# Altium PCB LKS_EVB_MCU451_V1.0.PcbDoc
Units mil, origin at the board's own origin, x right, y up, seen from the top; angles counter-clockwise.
Board outline 8180 x 3528.01 mil, 2 copper layers (Top Layer, Bottom Layer); 102 components, 121 nets, 428 pads, 143 vias.
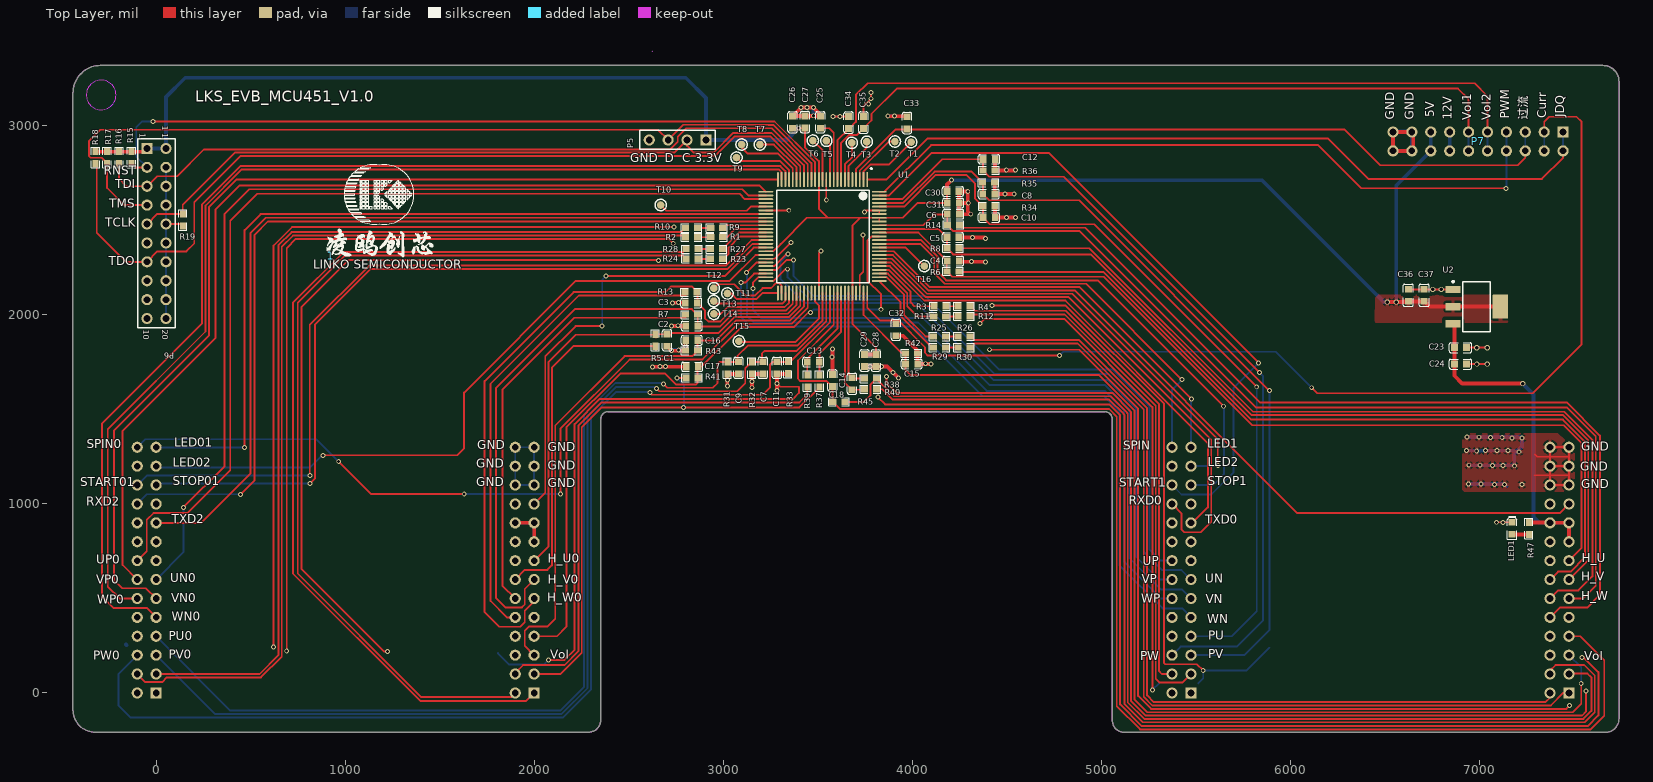
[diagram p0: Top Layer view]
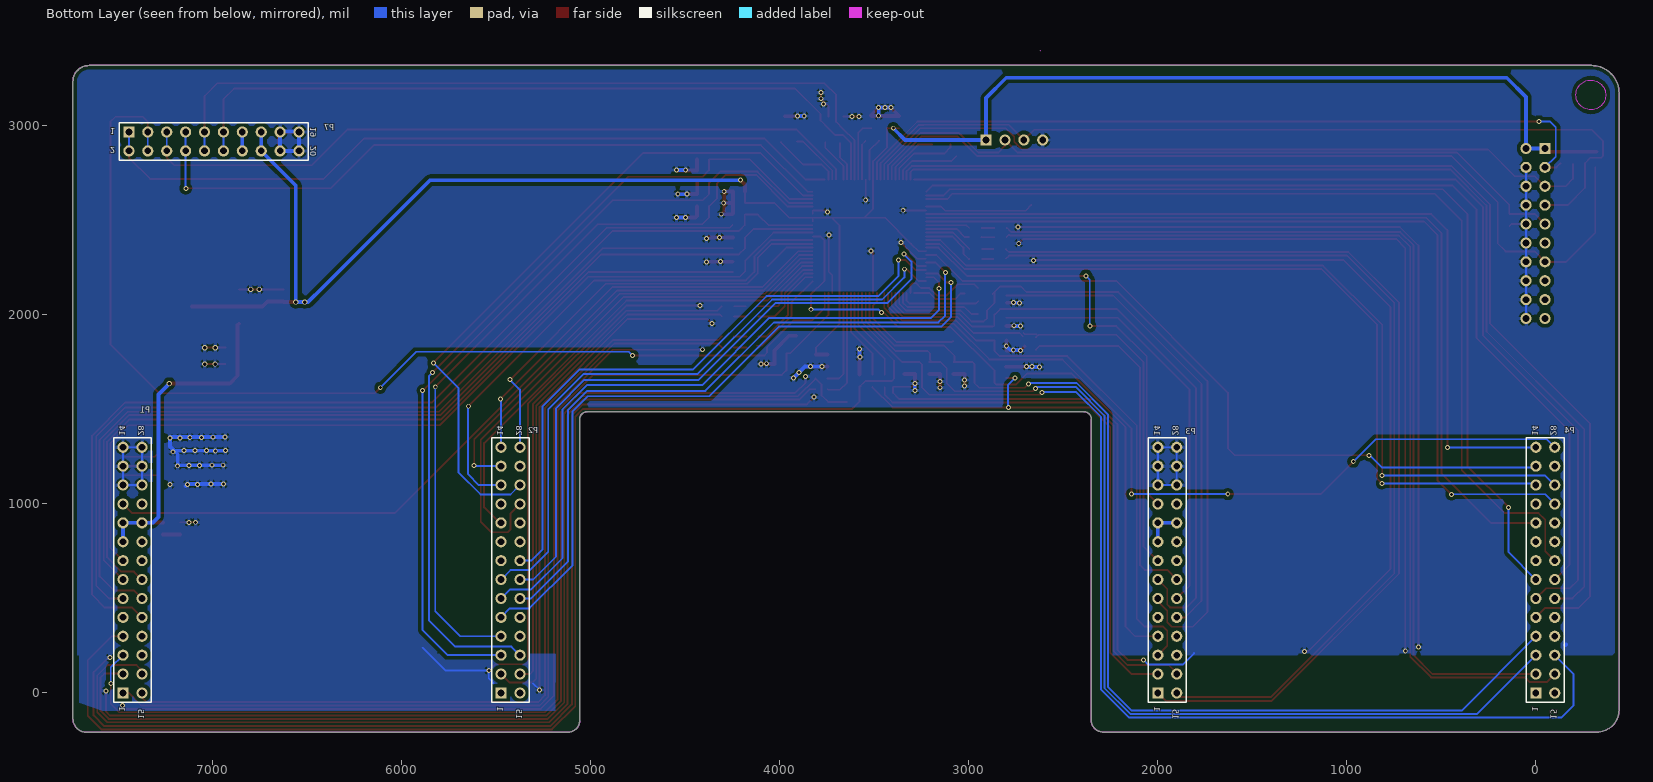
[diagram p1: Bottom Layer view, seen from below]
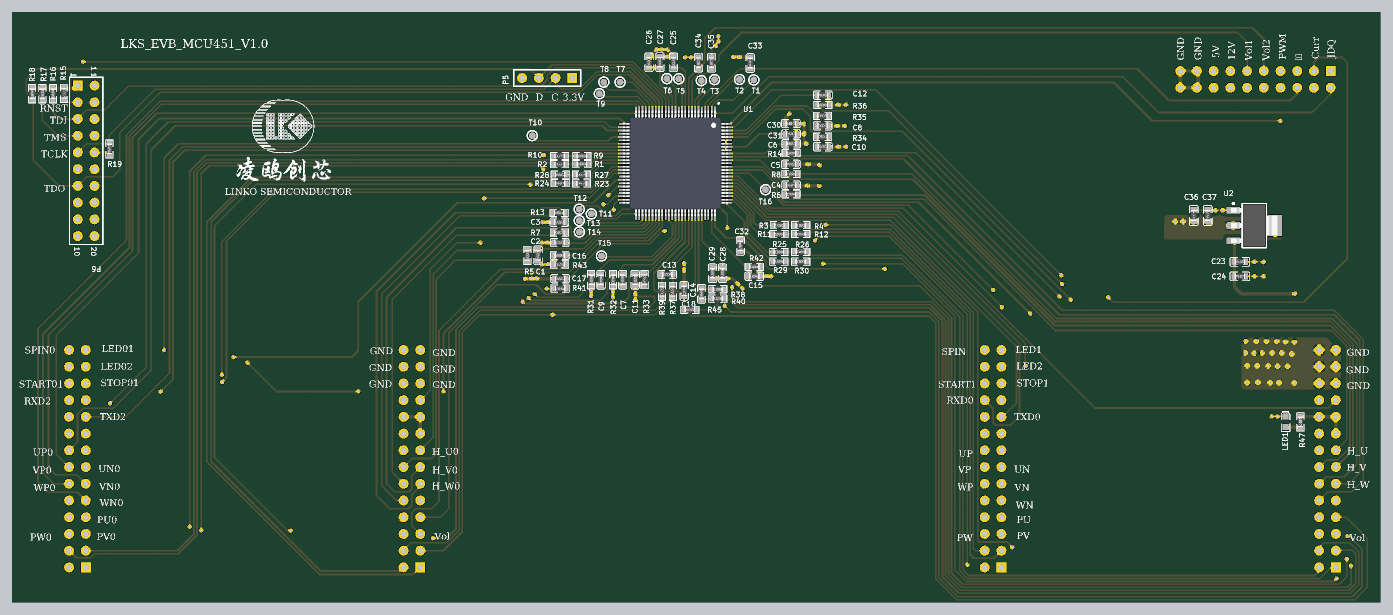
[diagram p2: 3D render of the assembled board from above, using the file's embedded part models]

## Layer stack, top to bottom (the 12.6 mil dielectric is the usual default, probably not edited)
Top Solder: solder mask 0.4, Solder Resist, Dk 3.5
Top Layer: signal copper 1.4
Dielectric1: dielectric 12.6, FR-4, Dk 4.8
Bottom Layer: signal copper 1.4
Bottom Solder: solder mask 0.4, Solder Resist, Dk 3.5

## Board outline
-440,-91 ccw(c-324,-91) -324,-207 2288.99,-207 ccw(c2288.99,-143.67) 2352.32,-143.67 2352.32,1448.33 cw(c2392,1448.33) 2392,1488.01 5018,1488.01 cw(c5018,1446.67) 5059.33,1446.67 5059.33,-146.33 ccw(c5121,-146.33) 5121,-208 7669,-208 ccw(c7669,-137) 7740,-137 7740,3235 ccw(c7654.99,3235) 7654.99,3320.01 -294.32,3320.01 ccw(c-294.32,3174.33) -440,3174.33

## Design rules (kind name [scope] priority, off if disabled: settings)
Clearance Clearance_1 [INPolygon] p1: gap=20 ignorepadtopadclearanceinfootprint=FALSE except(0: Arc-Hole Track-Hole SMDPad-Hole THPad-Hole Via-Hole Fill-Hole Poly-Hole Region-Hole Text-Hole)
Clearance [All] p2: gap=7.87 ignorepadtopadclearanceinfootprint=FALSE except(0: Arc-Hole Track-Hole SMDPad-Hole THPad-Hole Via-Hole Fill-Hole Poly-Hole Region-Hole Text-Hole)
ComponentClearance [All] p1: gap=0 collisioncheckmode=3 verticalgap=0 showdistances=FALSE
MinimumSolderMaskSliver [All] p1 off: minsoldermaskwidth=10
PolygonConnect [All] p1: connectstyle=Relief reliefconductorwidth=20 reliefentries=4 polygonreliefangle="90 Angle" airgapwidth=10
RoutingVias [All] p1: holewidth=28 width=50 viastyle="Through Hole" minholewidth=28 minwidth=50 maxholewidth=28 maxwidth=50
SilkToSilkClearance [All] p1 off: silktosilkclearance=10
SilkToSolderMaskClearance SilkscreenOverComponentPads [IsPad] p1 off: minsilkscreentomaskgap=10 clearancetoexposedcopper=TRUE
SolderMaskExpansion [All] p1: expansion=4 istentingtop=FALSE
Width [All] p1: maxlimit=100 minlimit=1 preferedwidth=10
26 further rules are at their usual default settings.

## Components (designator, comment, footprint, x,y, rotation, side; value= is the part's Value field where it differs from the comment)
1 "LKS_sign" LKS_LOGO2 924,2313 r0 top
C1 "10nF/16V" 0603C 2704,1866 r270 top
C2 "10nF/16V" 0603C 2833.5,1941.99 r180 top
C3 "10nF/16V" 0603C 2831.67,2063.99 r180 top
C4 "10nF/16V" 0603C 4217,2285 r0 top
C5 "10nF/16V" 0603C 4216,2410 r0 top
C6 "10nF/16V" 0603C 4218,2533 r0 top
C7 "1nF/16V" 0603C 3210,1720 r270 top
C8 "1nF/16V" 0603C 4406,2640 r0 top
C9 "1nF/16V" 0603C 3081,1720 r270 top
C10 "1nF/16V" 0603C 4407,2515 r0 top
C11 "1nF/16V" 0603C 3285,1720 r270 top
C12 "1nF/16V" 0603C 4407.01,2823.67 r0 top
C13 "1nF/10V" 0603C 3477,1751 r180 top
C14 "1nF/10V" 0603C 3682,1636 r270 top
C15 "100nF/50V" 0603C 3997,1741 r180 top
C16 "100nF/50V" 0603C 2834.01,1865.67 r0 top
C17 "1nF/50V" 0603C 2836,1726 r0 top
C18 "1nF/50V" 0603C 3578,1653 r270 top
C23 "10uF/10V" 0603C 6901,1827 r0 top
C24 "100nF/10V" 0603C 6901,1740 r0 top
C25 "100nF/50V" 0603C 3514,3020 r90 top
C26 "10uF/10V" 0603C 3368,3020 r90 top
C27 "100nF/10V" 0603C 3432.67,3020.99 r90 top
C28 "10uF/10V" 0603C 3808,1759 r270 top
C29 "100nF/10V" 0603C 3748,1759 r270 top
C30 "10uF/10V" 0603C 4216.01,2653.67 r0 top
C31 "100nF/10V" 0603C 4217,2592 r0 top
C32 "100pF/10V" 0603C 3914,1922 r270 top
C33 "100pF/10V" 0603C 3973,3016 r90 top
C34 "100pF/10V" 0603C 3664,3018 r90 top
C35 "100pF/10V" 0603C 3742,3018 r90 top
C36 "10uF/10V" 0603C 6625,2104 r90 top
C37 "100nF/10V" 0603C 6709,2104 r90 top
LED1 "LED" 0603D 7174,871 r90 top
P1 "Header 14X2A" HDR2X14_CEN 7475,0 r90 bottom
P2 "Header 14X2A" HDR2X14_CEN 5475,0 r90 bottom locked
P3 "Header 14X2A" HDR2X14_CEN 2000,0 r90 bottom locked
P4 "Header 14X2A" HDR2X14_CEN 0,0 r90 bottom locked
P5 "Header 4" HDR1X4 2909,2926 r180 top
P6 "Header 10X2A" HDR2X10_CEN -48,2881 r270 top
P7 "Header 10X2" HDR2X10 7444,2968 r180 top locked
R1 "20K1%" 0603R 2966,2411.5 r0 top value=K
R2 "20K1%" 0603R 2833,2411 r0 top value=K
R3 "20K1%" 0603R 4147,2046 r180 top value=K
R4 "20K1%" 0603R 4275,2046 r180 top value=K
R5 "2K" 0603R 2641,1866 r90 top value=K
R6 "2K" 0603R 4217,2231 r180 top value=K
R7 "2K" 0603R 2832,2002 r0 top value=K
R8 "2K" 0603R 4216,2353 r180 top value=K
R9 "20K1%" 0603R 2966,2460 r0 top value=K
R10 "20K1%" 0603R 2833,2460 r0 top value=K
R11 "20K1%" 0603R 4146,1992.5 r180 top value=K
R12 "20K1%" 0603R 4275,1993 r180 top value=K
R13 "2K" 0603R 2830,2120 r0 top value=K
R14 "2K" 0603R 4218,2477 r180 top value=K
R15 "10K" 0603R -130,2834 r270 top value=330
R16 "10K" 0603R -196,2832 r270 top value=330
R17 "10K" 0603R -260,2832 r270 top value=330
R18 "10K" 0603R -321,2832 r270 top value=330
R19 "10K" 0603R 141,2502 r90 top value=330
R23 "20K1%" 0603R 2964,2296 r0 top value=K
R24 "20K1%" 0603R 2836,2297 r0 top value=K
R25 "20K1%" 0603R 4144,1886 r180 top value=K
R26 "20K1%" 0603R 4275,1887 r180 top value=K
R27 "20K1%" 0603R 2964,2348 r0 top value=K
R28 "20K1%" 0603R 2836,2348 r0 top value=K
R29 "20K1%" 0603R 4144,1828 r180 top value=K
R30 "20K1%" 0603R 4275,1828 r180 top value=K
R31 "1K" 0603R 3022,1720 r270 top value=K
R32 "1K" 0603R 3152,1720 r270 top value=K
R33 "1K" 0603R 3342,1721 r270 top value=K
R34 "1K" 0603R 4406,2575 r0 top value=K
R35 "1K" 0603R 4405,2700 r0 top value=K
R36 "1K" 0603R 4407,2765 r0 top value=K
R37 "1K1%" 0603R 3510,1650 r90 top value=K
R38 "1K1%" 0603R 3779,1663 r180 top value=K
R39 "1K1%" 0603R 3445.33,1650.01 r90 top value=K
R40 "1K1%" 0603R 3779,1607 r180 top value=K
R41 "1K1%" 0603R 2836,1667 r180 top value=K
R42 "1K1%" 0603R 3997,1797 r180 top value=K
R43 "1K1%" 0603R 2833,1811 r0 top value=K
R45 "1K1%" 0603R 3612,1540 r0 top value=K
R47 "330R" 0603R 7263,870 r270 top value=330
T1 "TestP" TP-40 3995,2915 r0 top
T2 "TestP" TP-40 3909,2918 r0 top
T3 "TestP" TP-40 3760,2917 r0 top
T4 "TestP" TP-40 3681,2911 r0 top
T5 "TestP" TP-40 3546,2922 r0 top
T6 "TestP" TP-40 3475,2923 r0 top
T7 "TestP" TP-40 3195,2902 r0 top
T8 "TestP" TP-40 3098,2902 r0 top
T9 "TestP" TP-40 3071,2833 r0 top
T10 "TestP" TP-40 2669,2582 r90 top
T11 "TestP" TP-40 3023,2114 r0 top
T12 "TestP" TP-40 2950,2142 r90 top
T13 "TestP" TP-40 2950,2074 r90 top
T14 "TestP" TP-40 2951,2006 r90 top
T15 "TestP" TP-40 3083,1862 r90 top
T16 "TestP" TP-40 4064,2259 r90 top
U1 "LKS451" LQFP_100N 3526.01,2415.67 r270 top locked
U2 "AMS1117-3.3V" DCY0004A_M 6987,2044 r0 top

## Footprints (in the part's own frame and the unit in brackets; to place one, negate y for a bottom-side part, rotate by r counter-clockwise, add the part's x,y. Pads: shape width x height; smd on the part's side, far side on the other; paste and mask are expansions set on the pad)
0603C [mm]
  rect 0.9x0.95 smd: 1(-0.813,0) 2(0.813,0)
  silkscreen extent -1.42,-0.64 1.42,0.64, body extent -0.8,-0.4 0.8,0.4, height 0.45
0603D [mm]
  rect 0.9x0.9 smd: 1(-0.813,0) 2(0.813,0)
  silkscreen extent -1.47,-0.66 1.65,0.66
0603R [mil]
  rect 38x32 smd: 1(-32,0) 2(32,0)
  silkscreen extent -54,-22 54,22, body extent -31,-16 32,16, height 18
DCY0004A_M [mm] "SOT223, 4-Leads, Body 6.7x3.7mm, Pitch 2.3mm, IPC Low Density"
  rrect10% 2.05x1 smd: 1(-3.175,2.3) 2(-3.175,0) 3(-3.175,-2.3)
  rrect5% 2.05x3.25 smd: 4(3.175,0)
  silkscreen extent -3.3,-3.35 1.85,3.47, body extent -3.5,-3.25 3.5,3.25, height 1.62
HDR1X4 [mm] "Connector; Header; 4 Position"
  rect 1.5x1.5 hole 0.9: 1(0,0)
  round 1.5 hole 0.9: 2(2.54,0) 3(5.08,0) 4(7.62,0)
  silkscreen extent -1.27,-1.27 8.89,1.27
HDR2X10 [mm] "Connector; Header; 10x2 Position"
  rect 1.5x1.5 hole 0.9: 1(0,0)
  round 1.5 hole 0.9: 2(0,2.54) 3(2.54,0) 4(2.54,2.54) 5(5.08,0) 6(5.08,2.54) 7(7.62,0) 8(7.62,2.54) 9(10.16,0) 10(10.16,2.54) 11(12.7,0) 12(12.7,2.54) 13(15.24,0) 14(15.24,2.54) 15(17.78,0) 16(17.78,2.54) 17(20.32,0) 18(20.32,2.54) 19(22.86,0) 20(22.86,2.54)
HDR2X10_CEN [mm] "Connector; Header; 10x2 Position"
  rect 1.5x1.5 hole 0.9: 1(0,0)
  round 1.5 hole 0.9: 2(2.54,0) 3(5.08,0) 4(7.62,0) 5(10.16,0) 6(12.7,0) 7(15.24,0) 8(17.78,0) 9(20.32,0) 10(22.86,0) 11(0,2.54) 12(2.54,2.54) 13(5.08,2.54) 14(7.62,2.54) 15(10.16,2.54) 16(12.7,2.54) 17(15.24,2.54) 18(17.78,2.54) 19(20.32,2.54) 20(22.86,2.54)
  silkscreen extent -1.27,-1.27 24.13,3.81
HDR2X14_CEN [mm] "Connector; Header; 14x2 Position"
  rect 1.5x1.5 hole 0.9: 1(0,0)
  round 1.5 hole 0.9: 2(2.54,0) 3(5.08,0) 4(7.62,0) 5(10.16,0) 6(12.7,0) 7(15.24,0) 8(17.78,0) 9(20.32,0) 10(22.86,0) 11(25.4,0) 12(27.94,0) 13(30.48,0) 14(33.02,0) 15(0,-2.54) 16(2.54,-2.54) 17(5.08,-2.54) 18(7.62,-2.54) 19(10.16,-2.54) 20(12.7,-2.54) 21(15.24,-2.54) 22(17.78,-2.54) 23(20.32,-2.54) 24(22.86,-2.54) 25(25.4,-2.54) 26(27.94,-2.54) 27(30.48,-2.54) 28(33.02,-2.54)
  silkscreen extent -1.27,-3.81 34.29,1.27
LKS_LOGO2 [mil] "标?"
  silkscreen extent 70,167 440,482
LQFP_100N [mm] "TSQFP, 100-Leads, Body 16,0x16,0mm (max), Pitch 0,50mm, IPC Medium Density"
  rect 2x0.25 smd: 1(-7.625,6)
  oval 2x0.25 smd: 2(-7.625,5.5) 3(-7.625,5) 4(-7.625,4.5) 5(-7.625,4) 6(-7.625,3.5) 7(-7.625,3) 8(-7.625,2.5) 9(-7.625,2) 10(-7.625,1.5) 11(-7.625,1) 12(-7.625,0.5) 13(-7.625,0) 14(-7.625,-0.5) 15(-7.625,-1) 16(-7.625,-1.5) 17(-7.625,-2) 18(-7.625,-2.5) 19(-7.625,-3) 20(-7.625,-3.5) 21(-7.625,-4) 22(-7.625,-4.5) 23(-7.625,-5) 24(-7.625,-5.5) 25(-7.625,-6) 51(7.625,-6) 52(7.625,-5.5) 53(7.625,-5) 54(7.625,-4.5) 55(7.625,-4) 56(7.625,-3.5) 57(7.625,-3) 58(7.625,-2.5) 59(7.625,-2) 60(7.625,-1.5) 61(7.625,-1) 62(7.625,-0.5) 63(7.625,0) 64(7.625,0.5) 65(7.625,1) 66(7.625,1.5) 67(7.625,2) 68(7.625,2.5) 69(7.625,3) 70(7.625,3.5) 71(7.625,4) 72(7.625,4.5) 73(7.625,5) 74(7.625,5.5) 75(7.625,6)
  oval 0.25x2 smd: 26(-6,-7.625) 27(-5.5,-7.625) 28(-5,-7.625) 29(-4.5,-7.625) 30(-4,-7.625) 31(-3.5,-7.625) 32(-3,-7.625) 33(-2.5,-7.625) 34(-2,-7.625) 35(-1.5,-7.625) 36(-1,-7.625) 37(-0.5,-7.625) 38(0,-7.625) 39(0.5,-7.625) 40(1,-7.625) 41(1.5,-7.625) 42(2,-7.625) 43(2.5,-7.625) 44(3,-7.625) 45(3.5,-7.625) 46(4,-7.625) 47(4.5,-7.625) 48(5,-7.625) 49(5.5,-7.625) 50(6,-7.625) 76(6,7.625) 77(5.5,7.625) 78(5,7.625) 79(4.5,7.625) 80(4,7.625) 81(3.5,7.625) 82(3,7.625) 83(2.5,7.625) 84(2,7.625) 85(1.5,7.625) 86(1,7.625) 87(0.5,7.625) 88(0,7.625) 89(-0.5,7.625) 90(-1,7.625) 91(-1.5,7.625) 92(-2,7.625) 93(-2.5,7.625) 94(-3,7.625) 95(-3.5,7.625) 96(-4,7.625) 97(-4.5,7.625) 98(-5,7.625) 99(-5.5,7.625) 100(-6,7.625)
  silkscreen extent -9.22,-6.12 6.22,6.66, body extent -8,-8 8,8, height 1.61
TP-40 [mil] "测试"
  round 40 smd: 1(-0.39,-0.39)
  silkscreen extent -30,-30 30,30

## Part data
C1 C2 C3 C4 C5 C6 C7 C8 C9 C10 C11 C12: library part CAP, "Capacitor"
C13 C14 C15 C16 C17 C18 C23 C24 C25 C26 C27 C28 C29 C30 C31 C32 C33 C34 C35 C36 C37: library part C, "Capacitor"
LED1: "LED_Light"
P1 P2 P3 P4: "Header, 14-Pin, Dual row"
P5: "Header, 4-Pin"
P6 P7: "Header, 10-Pin, Dual row"
R1 R2 R3 R4 R5 R6 R7 R8 R9 R10 R11 R12 R13 R14 R15 R16 R17 R18 R19 R23 R24 R25 R26 R27 R28 R29 R30 R31 R32 R33 R34 R35 R36 R37 R38 R39 R40 R41 R42 R43 R45 R47: library part Res, "Resistor"
U1: library part LKS32MC451VCT8, "LKS32MC451VCT8--chip"
U2: library part CMP-019-00008-2, "Low-Dropout Linear Regulator, 1 A, 3.3 V, 0 to 125 degC, 4-Pin SOT223 (DCY), RoHS, Tape and Reel", Case/Package=SOT-223, Dropout Voltage=1.2V, Manufacturer="Texas Instruments", Max Input Voltage=15V, Max Operating Temperature=125°C, Max Ouput Current=1A, Min Input Voltage=2.5V, Min Operating Temperature=0°C, Min Supply Voltage=3.2V, Nominal Supply Current=5mA, Output Voltage=3.3V, Package Description="4-Pin Small Outline Transistor, Body 6.5 x 3.5 mm, Pitch 2.3 mm", Package Quantity=1000, Package Reference=DCY0004A

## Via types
v1: diameter 26, hole 16, Top Layer to Bottom Layer, 133 vias
v2: diameter 28, hole 18, Top Layer to Bottom Layer, 9 vias
v3: diameter 23.62, hole 15.75, Top Layer to Bottom Layer, 1 vias

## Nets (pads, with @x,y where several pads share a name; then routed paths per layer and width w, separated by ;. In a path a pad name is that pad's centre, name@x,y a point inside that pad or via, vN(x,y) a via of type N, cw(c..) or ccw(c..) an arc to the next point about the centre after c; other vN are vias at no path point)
5V: P3.9 P3.10 P3.24 | length 400
  Top Layer w20: P3.24 P3.10 P3.9
  Bottom Layer w20: P3.24 P3.10 P3.9
12V: P7.13 P7.14 | length 100
  Bottom Layer w20: P7.14 P7.13
+3.3V: C26.1 C27.1 C28.1 C29.1 C30.1 C31.1 C36.1 C37.1 P5.1 P6.1 P6.11 P7.15 P7.16 R15.1 R16.1 R17.1 R18.1 U1.14 U1.42 U1.71 U1.92 U1.93 U2.2 U2.4 | length 11199
  Top Layer w9.84: C26.1 v1(3399.84,2988) 3431.68,2988 C27.1 3432.67,2887.6 3506.32,2813.95 U1.14 3506.32,2560.68 3552.9,2514.1 3725,2514.1 ; C28.1 3808,1829 3683.49,1953.51 U1.71 3683.49,2472.59 3725,2514.1 ; U1.92 U1.93 ; C30.1 4185,2652.68 C31.1 4027,2592 3949.1,2514.1 U1.93 ; 3725,2514.1 U1.93
  Top Layer w10: U1.42 3225.89,2337.01 3265.82,2337.01 3304,2375.19 3442.91,2514.1 3552.9,2514.1
  Top Layer w20: R18.1 R17.1 R16.1 -130,2864 -65,2864 P6.1 ; C29.1 C28.1 ; C30.1@4185,2652.68 4185,2690 v1(4208,2713) ; v2(6514,2068) v2(6561,2068) ; v2@6561,2069 6623,2069 6625,2071 6625.5,2071.5 6708.5,2071.5 C37.1 6709.98,2072 6737.98,2044 U2.2 U2.4
  Bottom Layer w20: P6.1 P6.11 52,3153 154,3255 2802,3255 2909,3148 P5.1 3337.84,2926 v1(3399.84,2988) ; v1(4208,2713) 5851,2713 6417.5,2146.5 6496,2068 v2(6514,2068) v2(6561,2068) 6561,2685 P7.16 P7.15
+5V: C23.1 C24.1 P1.9 P1.10 P1.24 R47.1 U2.3 | length 1999
  Top Layer w20: U2.3 6869,1946.45 C23.1 C24.1 6869,1678 6910,1637 v2(7230,1637) ; R47.1 7373,902 P1.24 P1.10 P1.9
  Bottom Layer w20: v2(7230,1637) 7288,1579 7288,1521 7288,931 7319,900 P1.24 P1.10 P1.9
GND: C1.2 C2.2 C3.2 C4.2 C5.2 C6.2 C7.2 C8.2 C9.2 C10.2 C11.2 C12.2 C15.1 C16.1 C17.1 C18.1 C23.2 C24.2 C25.2 C26.2 C27.2 C28.2 C29.2 C30.2 C31.2 C32.2 C33.2 C34.2 C35.2 C36.2 C37.2 LED1.2 P1.12 P1.13 P1.14 P1.26 P1.27 P1.28 P3.12 P3.13 P3.14 P3.26 P3.27 P3.28 P5.4 P6.12 P6.13 P6.14 P6.15 P6.16 P6.17 P6.18 P6.19 P6.20 P7.17 P7.18 P7.19 P7.20 R19.1 R31.2 R32.2 R33.2 R34.2 R35.2 R36.2 R42.1 R43.1 U1.12 U1.31 U1.44 U1.62 U1.73 U1.94 U1.95 U2.1 | length 48278.9
  Top Layer w9.84: P6.15 130,2481 R19.1 ; U1.44 3273.56,2297.56 v1(3360,2384) ; U1.31 v3(3348,2553.47) ; U1.62 3506.32,2326.32 v1(3518,2338) ; v1(3545.69,2607.31) U1.12 ; U1.73 3722.86,2210.86 3741,2229 v1(3741,2422) ; v1(3748,2545) 3756.47,2553.47 U1.95 U1.94 ; v1(7091,903) LED1.2 ; 7292,1152 7375,1152 ; 7294,1263 7307.12,1249.88 7375,1249.88 ; P1.28 7375,1249.88 ; P1.28@7395,1302 7473,1302 P1.14 P1.13 ; 7474.11,1149.16 7471.27,1152 7375,1152 ; 7474.27,1249.88 7375,1249.88 ; 7375,1152 P1.26 P1.12 P1.13 ; 7375,1152 P1.27 ; P1.27 P1.13 ; P1.27 7375,1249.88
  Top Layer w10: v1(621,243) 621,2367.17 718.83,2465 v1(2739.18,2465) ; v1(691,221) 691,2354 739.49,2402.49 2712.51,2402.49 v1(2736,2379) ; v1(1225,220) 1205,220 770,655 770,2043 1018,2291 v1@2659,2291 ; v1(2076,175) 2160,175 2214,229 2214,1422.83 2347.17,1556 3370,1556 3401,1587 3401,1620 3302,1620 v1@3285,1637 ; v1(3582,3050) v1(3618,3050) C34.2 ; C35.2 3742,3103 v1(3783,3144) v1(3783,3176) ; v1(3819,1565) 3857,1527 5043,1527 5100.59,1469.41 5100.59,-60.59 5215,-175 7574.53,-175 7631,-118.53 7631,110 7554,187 v1(7544,187) ; v1(3864,1675) 3864,1642 3918.49,1587.51 5057.88,1587.51 5153.9,1491.49 5153.9,1489.32 5158.51,1484.71 5158.51,-43.12 5235.16,-119.77 7544.06,-119.77 7566,-97.83 v1(7566,10) ; v1(4360,1955) 4384,1979 4804.83,1979 5271.2,1512.63 v1(5271.2,15.8) ; v1(4409,1816) 4883.83,1816 5195,1504.83 5195,-15.22 5263.96,-84.18 7461.82,-84.18 v1(7479,-67) ; v1(4423,2049) 4812.83,2049 5332.6,1529.24 5332.6,1282.44 5333,1282.04 5333,1217.96 5332.6,1217.56 5332.6,158.4 5339,152 5507,152 v1(5540,119) ; C36.2@6625,2135 6625.45,2134.55 6755,2134.55 U2.1 ; C24.2 v2(6988,1740) v2(7043,1740) ; C23.2 v2(6987.5,1827) 7042,1827 v2(7043,1826)
  Top Layer w20: v1(2626,1725) 2627,1726 C17.1 ; C1.2 v1(2727,1811) R43.1 2801,1864.67 C16.1 ; v1(2727.01,1941.99) C2.2 ; v1(2731,2064) C3.2 ; v1(3022,1623) v1(3022,1655.5) R31.2 C9.2 ; v1(3152,1615) v1(3152,1648) R32.2 C7.2 ; v1(3285,1600) 3285,1637 C11.2 3341,1688 R33.2 ; C25.2 3477,3052 C26.2 v1(3413,3097) v1(3444,3097) v1(3477,3097) C25.2@3519,3055 ; C18.1 v1(3578,1819) ; C29.2 v1(3778,1727) C28.2 v1(3838,1727) 3868,1727 v1(3899,1696) v1@3927.5,1667.5 ; v1@3871,3051 C33.2@3973,3051 ; C32.2 3951,1890 4029,1812 R42.1 C15.1 v1(4099,1741) ; C5.2 v1(4319,2410) 4383,2410 v1(4389,2404) ; C4.2@4249,2282 v1(4315,2282) 4387,2282 v1(4388,2281) ; C31.2 v1@4294.33,2592 ; v1@4295,2653 v1(4294.33,2653.67) ; v1@4298,2593 v1(4297,2592) v1@4294.33,2592 ; R35.2 4437,2641 C8.2 v1(4540,2640) ; R34.2 4438,2523 4446,2515 v1@4486,2515 ; R36.2 4545,2765 v1(4547,2767) ; R36.2 C12.2 ; v1(4499,2515) v1(4547,2515) ; P7.17 P7.19 P7.20 P7.18 6651,2875 P7.17@6651,2972 ; v1@4294.33,2592 v1(4294.33,2653.67) ; v1@4294.33,2592 4294.33,2548.67 v1(4310,2533) C6.2 4248.01,2534.99 C30.2 v1(4294.33,2653.67)
  Bottom Layer w9.84: P6.20 P6.19 P6.18 P6.17 P6.16 P6.15 P6.14 P6.13 P6.12 ; P3.28 P3.27 P3.26 P3.12 P3.13 P3.14 1928,1300 P3.28@1920,1292 ; P1.28@7374,1303 7377,1300 P1.14 P1.13 P1.12 P1.26 P1.27 P1.28
  Bottom Layer w10: 1808,211 1869,150 2051,150 v1(2076,175) ; v1(5271.2,15.8) 5306.41,51 ; 5514,51 5540,77 v1(5540,119) 5770,119 5890,239
  Bottom Layer w20: -160,256 -156.6,252.6 ; v1(2626,1725) 2692,1725 v1(2695,1728) ; v1(2727,1811) 2730,1814 v1(2765,1814) 2781,1814 v1(2802,1835) ; v1(2727.01,1941.99) 2759.99,1941.99 v1(2761,1943) ; v1(2731,2064) 2762,2064 v1(2763,2065) ; v1(3285,1600) 3286,1601 v1(3286,1637) ; v1(3413,3097) v1(3444,3097) v1(3477,3097) v1(3477,3054) ; v1(3577,1778) 3578,1779 v1(3578,1819) ; v1(3778,1727) v1(3838,1727) 3867,1727 v1(3927,1667) ; v1(3871,3053) v1(3907,3053) ; v1(4492,2639) 4539,2639 v1(4540,2640) ; v1(4498,2767) v1(4547,2767) ; v1(4499,2515) v1(4547,2515) ; P7.19 P7.20 P7.18 P7.17 6640,2972 P7.19@6545,2972 ; v1(6934,1282) v1(7033,1282) v1(7094,1282) v1(7152,1282) v1@7205,1282 ; v1(6935,1354) 7122,1354 7221,1354 v1(7227,1348) 7227,1304 v1@7205,1282 ; v1(6944,1105) 7134,1105 v1(7135,1104) 7145,1094 ; v1(6945,1205) v1(7004,1205) 7183,1205 v1(7186,1202) 7186,1263 v1@7205,1282 ; v1(7211,1276) v1@7205,1282
  other v1: 7126,902 7226,1102 7081,1103 7009,1106 7126,1203 7070,1204 6987,1280 7174,1350 7060,1352 7122,1352 6999,1353 2665,1727 4071,1742 2659,2288 3768,3117
  other v2: 6755,2135 6799,2135
GND0: P3.16 R39.1 | length 2899.1
  Top Layer w9.84: P3.16 1900,106 1942,148 2161,148 2234,221 2234,1413 2358,1537 3404,1537 3445.33,1578.33 R39.1
GND1: P1.16 R40.1 | length 5934.3
  Top Layer w9.84: R40.1 3841.95,1607 3896.95,1552 5043.17,1552 5118.39,1476.78 5118.39,1474.61 5123,1470 5123,-57.83 5220.45,-155.28 7558.77,-155.28 7611.72,-102.34 7611.72,92.28 7556,148 7404,148 7375,119 P1.16
HALL_U: C4.1 P1.8 R6.2 U1.89 | length 4858.6
  Top Layer w9.84: U1.89 4033.64,2435.36 4183,2286 4183,2230 4211,2202 5014,2202 5799.55,1416.45 7447.45,1416.45 7540.95,1322.95 7540.95,765.95 P1.8
HALL_U0: C1.1 P3.8 R5.2 U1.57 | length 2616.6
  Top Layer w9.84: P3.8 2076.57,776.57 2076.57,1752.57 2219,1895 2631,1895 R5.2@2645,1881 ; R5.2 C1.1 C1.1@2710,1904 ; C1.1@2714,1887 2732,1905 2976,1905 3059.85,1988.85 3348.01,1988.85 3407.9,2048.73 U1.57
HALL_V: C5.1 P1.7 R8.2 U1.90 | length 5026.5
  Top Layer w9.84: U1.90 4138.96,2455.04 C5.1 R8.2 4217,2320 4946.11,2320 5796.11,1470 7444,1470 7577,1337 7577,702 P1.7
HALL_V0: C2.1 P3.7 R7.2 U1.56 | length 3378.7
  Top Layer w9.84: P3.7 1950,550 1950,468 1935,453 1848,453 1798,503 1798,1613 2216,2031 2835,2031 R7.2 2865.5,2000.5 C2.1 ; C2.1@2872,1939 2984,1939 3051.57,2006.57 3340.68,2006.57 3388.21,2054.1 U1.56
HALL_W: C6.1 P1.6 R14.2 U1.91 | length 5294.9
  Top Layer w9.84: U1.91 4059.73,2474.73 4116,2531 4186,2531 R14.2 4185,2476 4217,2444 4887,2444 5821,1510 7466,1510 7617,1359 7617,567 7550,500 P1.6
HALL_W0: C3.1 P3.6 R13.2 U1.55 | length 3704.3
  Top Layer w9.84: P3.6 2000,484 1950,434 1950,373 1927,350 1816,350 1738,428 1738,1650 2208.72,2120.72 2695,2120.72 2725.28,2151 2834,2151 R13.2@2874,2111 ; R13.2 2863.67,2118.33 C3.1 2903.38,2024.28 2903.38,1983.62 2921,1966 2985.95,1966 3044.23,2024.28 3333.34,2024.28 3368.53,2059.47 U1.55
HU: P1.21 R6.1 | length 4528.2
  Top Layer w9.84: R6.1@4248,2227 5014.05,2227 5795.05,1446 7442.95,1446 7559.28,1329.66 7559.28,717.28 7484.32,642.32 7417.32,642.32 P1.21
HU0: P3.21 R5.1 | length 1878.4
  Top Layer w9.84: P3.21 1951,651 2070,651 2094.28,675.28 2094.28,1721.28 2209,1836 2624,1836 R5.1@2645,1815
HV: P1.20 R8.1 | length 4766.9
  Top Layer w9.84: R8.1 4938.16,2353 5803.45,1487.72 7451.34,1487.72 7599.28,1339.77 7599.28,616.28 7525.32,542.32 7417.32,542.32 P1.20
HV0: P3.20 R7.1 | length 2262
  Top Layer w9.84: P3.20 1832,568 1832,1604 2213,1985 2804,1985
HW: P1.19 R14.1 | length 5006.6
  Top Layer w9.84: R14.1 4265.28,2461.72 4915.28,2461.72 5840,1537 7464.05,1537 7639,1362.05 7639,520 7571,452 7427,452 P1.19
HW0: P3.19 R13.1 | length 2542.5
  Top Layer w9.84: P3.19 1855.95,400 1769,486.95 1769,1636 2236,2103 2802,2103
JDQ: P7.1 P7.2 U1.1 | length 4043.2
  Top Layer w9.84: U1.1 3863.87,2715.87 4082,2934 6199,2934 6413,2720 7332,2720 7444,2832 P7.2
  Bottom Layer w9.84: P7.2 P7.1
JTAG_RNST: P6.2 R15.2 U1.15 | length 4112.6
  Top Layer w9.84: R15.2 -109,2781 P6.2 ; v1@-16,3023.72 3245.46,3023.72 3245.74,3023.43 3271.78,3023.43 3486.64,2808.58 U1.15
  Bottom Layer w9.84: P6.2 -105,2838 -105,2993 -74,3024 v1(-16,3024)
JTAG_TCLK: P5.2 P6.5 R19.2 U1.18 | length 3926.8
  Top Layer w9.84: P6.5 6,2535 7,2534 R19.2 141,2583.33 416.25,2858.58 2741.58,2858.58 P5.2 2809,2894 2844.42,2858.58 2949,2858.58 3053.42,2963 3231.01,2963 3231.32,2962.69 3257.36,2962.69 3427.58,2792.47 U1.18
JTAG_TDI: P6.3 R16.2 U1.17 | length 4043.1
  Top Layer w9.84: R16.2 -196,2720 -157,2681 P6.3 5,2734 111,2734 253.3,2876.3 2719.15,2876.3 2760,2917.15 2760,2944 2804,2988 3257.11,2988 3447.27,2797.84 U1.17
JTAG_TDO: P6.7 R18.2 U1.19 | length 4673.2
  Top Layer w9.84: R18.2@-314,2782 -314,2434 -161,2281 P6.7 7,2336 160,2336 202,2378 202,2597 445.86,2840.86 2956.34,2840.86 3060.45,2944.98 3250.02,2944.98 3407.9,2787.1 U1.19
JTAG_TMS: P5.3 P6.4 R17.2 U1.16 | length 4645.5
  Top Layer w9.84: P6.4 -169,2581 -260,2672 R17.2 -260,2803 -288.79,2831.79 -346.79,2831.79 -356,2841 -356,2919 -295,2980 2655,2980 P5.3 2789,3006 3238.12,3006 3238.4,3005.72 3264.45,3005.72 3466.95,2803.21 U1.16
LED1: P2.14 U1.84 | length 2230.2
  Top Layer w9.84: U1.84 3903.61,2336.93 4093.26,2147.28 4886.66,2147.28 5477,1556.95 v1(5477,1555)
  Bottom Layer w9.84: P2.14 5476,1301 v1@5476,1554
LED01: P4.14 U1.32 | length 4411.3
  Top Layer w9.84: v1(468,1299) 468,2449 552.78,2533.78 U1.32
  Bottom Layer w9.84: P4.14 1,1299 v1(468,1299)
LED2: P2.13 U1.82 | length 2471.3
  Top Layer w9.84: U1.82 3892.87,2297.56 4078.58,2111.85 4847.15,2111.85 5617,1342 v1@5617,1202
  Bottom Layer w9.84: P2.13 5614,1200 v1(5618,1204)
LED02: P4.13 U1.43 | length 3863.9
  Top Layer w9.84: v1(883,1257) 884,1258 1592,1258 1629,1295 1629,1589 2220,2180 3034.22,2180 3171.47,2317.25 U1.43
  Bottom Layer w9.84: P4.13 8,1192 813,1192 v1@879,1258
LED3: P1.11 U1.83 | length 4233.4
  Top Layer w9.84: U1.83 3898.24,2317.25 4085.92,2129.57 4859.43,2129.57 6036,953 7428,953 P1.11
LED03: P3.11 U1.41 | length 2354.8
  Top Layer w9.84: P3.11 2058.85,1058.85 2058.85,1780.85 2219,1941 v1(2360,1941) ; v1(2380,2207) 3011.11,2207 3160.73,2356.62 U1.41
  Bottom Layer w9.84: v1(2360,1941) 2360,2187 v1(2380,2207)
NetLED1_1: LED1.1 R47.2 | length 89.4
  Top Layer w20: LED1.1 7175,838 R47.2
NetR1_1: R1.1 R2.2 | length 69.2
  Top Layer w9.84: R2.2 2933.5,2411 R1.1
NetR3_1: R3.1 R4.2 | length 64
  Top Layer w9.84: R3.1 R4.2
NetR9_1: R9.1 R10.2 | length 69
  Top Layer w9.84: R10.2 R9.1
NetR11_1: R11.1 R12.2 | length 65.2
  Top Layer w9.84: R11.1 4242.5,1992.5 R12.2
NetR23_1: R23.1 R24.2 | length 64.4
  Top Layer w9.84: R24.2 2869,2296 R23.1
NetR25_1: R25.1 R26.2 | length 67.4
  Top Layer w9.84: R25.1 4242,1886 R26.2
NetR27_1: R27.1 R28.2 | length 64
  Top Layer w9.84: R28.2 R27.1
NetR29_1: R29.1 R30.2 | length 67
  Top Layer w9.84: R29.1 R30.2
NetT1_1: T1.1 U1.2 | length 359.5
  Top Layer w10: U1.2 3742.54,2758.68 3778.86,2795 3875,2795 T1.1
NetT2_1: T2.1 U1.3 | length 297.7
  Top Layer w10: U1.3 3722.86,2764.28 3876.19,2917.61 T2.1
NetT3_1: T3.1 U1.6 | length 240.4
  Top Layer w9.84: U1.6 3663.8,2788.86 3759.61,2884.66 T3.1
NetT4_1: T4.1 U1.7 | length 211
  Top Layer w9.84: U1.7 3644.12,2796.12 3682,2834 3682,2909.21 T4.1
NetT5_1: T5.1 U1.11 | length 213.9
  Top Layer w9.84: T5.1 3565.38,2901.84 U1.11
NetT6_1: T6.1 U1.13 | length 228.1
  Top Layer w9.84: T6.1 3526.15,2871.06 3526.15,2716.01 U1.13
NetT7_1: T7.1 U1.20 | length 309.1
  Top Layer w9.84: T7.1 3268.34,2901.61 3388.21,2781.73 U1.20
NetT8_1: T8.1 U1.21 | length 392.2
  Top Layer w9.84: T8.1 3097.61,2886.39 3130,2854 3290.89,2854 3368.53,2776.36 U1.21
NetT9_1: T9.1 U1.22 | length 365.8
  Top Layer w9.84: T9.1@3063.8,2839.42 3067.03,2839.42 3091.45,2815 3300.27,2815 3348.84,2766.43 U1.22
NetT13_1: T13.1 U1.53 | length 430.9
  Top Layer w9.84: T13.1 2964.28,2059.72 3313.21,2059.72 3329.16,2075.66 U1.53
NetT14_1: T14.1 U1.54 | length 472.6
  Top Layer w9.84: T14.1 2987.61,2005.61 3024,2042 3326,2042 3348.84,2064.84 U1.54
NetT15_1: T15.1 U1.61 | length 620.6
  Top Layer w9.84: T15.1 3088,1857 3383.05,1857 3508,1981.95 3508,2049.05 3486.64,2070.42 U1.61
NetT16_1: T16.1 U1.85 | length 278.8
  Top Layer w9.84: U1.85 3966.38,2356.62 T16.1
OC: C18.2 P1.4 R45.1 U1.66 | length 7070.2
  Top Layer w9.84: C18.2@3574,1621 3574,1624.02 3548.02,1650 3409,1650 3396,1663 3396,1759 3585.06,1948.06 U1.66 ; C18.2 3578,1542 R45.1 3616.75,1503.25 5041.44,1503.25 5082.57,1462.12 5082.57,-69.68 5205.69,-192.79 7590.2,-192.79 7662,-121 7662,173 7535,300 P1.4
OC0: C17.2 P3.4 R41.1 U1.88 | length 3721.8
  Top Layer w9.84: P3.4 2121,300 2171,350 2171,1405 2456,1690 2693,1690 2750.28,1632.72 2856.72,1632.72 2864,1640 2864,1704 3095.7,1935.7 3373.7,1935.7 3451,2013 3452,2012 v1(3462,2012)
  Top Layer w10: U1.88 3785.67,2415.67 3763,2393 3763,2182 3836,2109 v1(3836,2030)
  Bottom Layer w9.84: v1(3462,2012) 3479,2029 v1@3836,2029
OPA0_IN: R11.2 U1.78 | length 422.4
  Top Layer w9.84: U1.78 3871.39,2218.82 3974.43,2115.78 3974.43,2046.07 4028,1992.5 R11.2
OPA0_IP: R3.2 U1.79 | length 418.8
  Top Layer w9.84: U1.79 3876.76,2238.51 3992.15,2123.12 3992.15,2066 4012.15,2046 R3.2 R3.2@4098.15,2046
OPA1_IN: R29.2 U1.76 | length 493.5
  Top Layer w9.84: U1.76 3939,2066.66 3939,1993 4095,1837 R29.2@4122,1837 ; R29.2@4103,1837 R29.2
OPA1_IP: R25.2 U1.77 | length 478.8
  Top Layer w9.84: U1.77 3866.02,2199.14 3956.72,2108.45 3956.72,2000.34 4071.05,1886 R25.2
OPA2_IN: C14.2 R40.2 U1.69 | length 593.4
  Top Layer w9.84: U1.69 3644.12,1641.88 C14.2 3744,1604 R40.2
OPA2_IP: C14.1 R38.2 U1.70 | length 522.1
  Top Layer w9.84: U1.70 3663.8,1686.2 C14.1 3687,1663 R38.2
OPA3_IN: C13.2 R39.2 U1.67 | length 499.5
  Top Layer w9.84: R39.2 3445.33,1768.33 3604.75,1927.75 U1.67
OPA3_IP: C13.1 R37.2 U1.68 | length 478.9
  Top Layer w9.84: R37.2@3510,1684 3510,1797 3624.43,1911.43 U1.68
OPA4_IN: R27.2 U1.37 | length 266
  Top Layer w9.84: R27.2 3083.36,2435.36 U1.37
OPA4_IP: R23.2 U1.38 | length 298.1
  Top Layer w9.84: R23.2 3001,2296 3029,2324 3029,2355.95 3088.73,2415.67 U1.38
OPA5_IN: R9.2 U1.35 | length 233.9
  Top Layer w9.84: R9.2 3012.73,2474.73 U1.35
OPA5_IP: R1.2 U1.36 | length 245.8
  Top Layer w9.84: R1.2 3020.5,2411.5 3064.04,2455.04 U1.36
P0.0: P1.5
P1.7: T10.1 U1.30 | length 578.4
  Top Layer w9.84: T10.1@2669,2582 2699.5,2551.5 3125,2551.5 3146.65,2573.15 U1.30
P2.9: T11.1 U1.51 | length 292.5
  Top Layer w9.84: T11.1 3042.39,2113.61 3072,2084 3176,2084 3207.48,2115.48 U1.51
P2.10: T12.1 U1.52 | length 463.9
  Top Layer w9.84: T12.1 2971.07,2162.28 3057.72,2162.28 3116.97,2103.03 3169.97,2103.03 3208.95,2142 3253.23,2142 3278.87,2167.64 3297.12,2167.64 3309.47,2155.3 U1.52
P10: P7.7 P7.8 U1.100 | length 3812.4
  Top Layer w9.84: U1.100 3852.89,2651.89 4100,2899 6148,2899 6377,2670 v1(7143,2670)
  Bottom Layer w9.84: v1(7143,2670) 7144,2671 P7.8 P7.7
PE3: C33.1 P7.5 P7.6 U1.4 | length 3915.9
  Top Layer w9.84: U1.4 3703.17,2773.17 3912,2982 3973,2982 6287,2982 6477,2792 7204,2792 7244,2832 P7.6
  Bottom Layer w9.84: P7.6 P7.5
PFC_CURRENT: C32.1 P7.3 P7.4 U1.75 | length 5737.4
  Top Layer w9.84: U1.75 3762.23,2037.77 3829,1971 3926,1971 4068,1829 4068,1800 4083,1785 v1(4779,1785) ; v1(6114,1615) 6143,1586 7284,1586 7542,1844 7542,3022 7515,3049 7371,3049 7344,3022 P7.3
  Bottom Layer w9.84: v1(4779,1785) 4799,1805 5924,1805 v1(6114,1615) ; P7.4 P7.3
PGND: P1.2 R38.1 R45.2 | length 6000
  Top Layer w9.84: R45.2 3745,1540 3778.8,1573.8 3778.8,1630.8 R38.1 3904.28,1569.72 5050.5,1569.72 5136.1,1484.12 5136.1,1481.95 5140.72,1477.34 5140.72,-50.5 5227.79,-137.57 7551.43,-137.57 7594,-95 7594,82 7573,103 7478,103 P1.2
PGND0: P3.2 R37.1 R41.2 | length 3059.4
  Top Layer w9.84: P3.2 2138.05,100 2251.72,213.66 2251.72,1405.66 2357.05,1511 3403.05,1511 3510,1617.95 R37.1 R37.1@3510,1620 ; v1(2755,1667) R41.2
  Bottom Layer w9.84: v1(2755,1667) 2792,1630 v1@2792,1511
  other v1: 2791,1511
PGND1: P3.1 R28.1 | length 5203.1
  Top Layer w9.84: P3.1 1957.68,-42.32 1398.27,-42.32 724,631.95 724,2065 992,2333 2789,2333 R28.1
PGND2: P4.2 R10.1 | length 5048.5
  Top Layer w9.84: P4.2 547,100 647,200 647,2368 717,2438 2774.91,2438 2796.91,2460 R10.1
PGND3: P4.1
PGND4: P1.1 R30.1 | length 4888
  Top Layer w9.84: R30.1 4328,1849 4876,1849 5225.28,1499.72 5225.28,-20.34 5271.33,-66.39 7379.61,-66.39 7446,0 P1.1
PGND5: 
PGND6: 
PU: C10.1 P2.4 R34.1 U1.96 | length 4202.2
  Top Layer w9.84: U1.96 3958.15,2573.15 4126,2741 4287,2741 4332,2696 4332,2617 R34.1 4375,2574 C10.1 4410,2480 4963,2480 v1(5823,1620)
  Bottom Layer w9.84: P2.4 5691,300 5823,432 v1(5823,1620)
PU0: C9.1 P4.4 R31.1 U1.63 | length 5638.5
  Top Layer w9.84: v1(2684,1635) 2704,1615 2946,1615 2971,1640 2971,1742 2981,1752 R31.1 C9.1 3076,1757 3076,1784 3130,1838 3391,1838 3526.01,1973.01 U1.63
  Bottom Layer w9.84: P4.4 393,-93 2139,-93 2264.57,32.57 2264.57,1474.68 2429.89,1640 2678,1640 v1@2684,1634
PV: C8.1 P2.3 R35.1 U1.97 | length 4384.7
  Top Layer w9.84: U1.97 3952.79,2592.84 4118.66,2758.72 4314.28,2758.72 R35.1 4374,2699 C8.1 4407,2607 4883,2607 v1(5890,1600)
  Bottom Layer w9.84: P2.3 5758,200 5890,332 v1(5890,1600)
PV0: C7.1 P4.3 R32.1 U1.64 | length 5627.9
  Top Layer w9.84: v1(2647,1611) 2662,1596 3075,1596 3117,1638 3117,1717 R32.1 C7.1@3196,1752 ; C7.1@3196,1751 C7.1@3196,1752 ; C7.1 C7.1@3196,1752 ; U1.64 3545.69,1967.64 3387.05,1809 3218,1809 3205,1796 3205,1761 C7.1@3196,1752
  Bottom Layer w9.84: P4.3 310.72,-110.72 2146.34,-110.72 2282.28,25.23 2282.28,1467.34 2432.95,1618 2640,1618 v1(2647,1611)
PW: C12.1 P2.17 R36.1 U1.98 | length 4477.6
  Top Layer w9.84: U1.98 3947.42,2612.52 4158.57,2823.67 C12.1 R36.1 ; R36.1 4409,2731 4802,2731 v1(5838.5,1694.5)
  Bottom Layer w9.84: P2.17 5420,245 5717,245 5857,385 5857,1676 v1(5838.5,1694.5)
PW0: C11.1 P4.17 R33.1 U1.65 | length 6045.2
  Top Layer w9.84: v1(2612,1589) 2623,1578 3209,1578 3247,1616 3247,1737 3262,1752 C11.1 3355.11,1752 3565.38,1962.27 U1.65
  Bottom Layer w9.84: P4.17 -200,100 -200,-64 -134,-130 2152.11,-130 2300,17.89 2300,1460 2432,1592 2609,1592 v1(2612,1589)
RSTN: C25.1 U1.10 | length 329.1
  Top Layer w9.84: C25.1 3561,2988 3585.06,2963.94 U1.10
RXD0: P2.25 U1.81 | length 2921.6
  Top Layer w9.84: U1.81 3887.5,2277.88 4071.24,2094.14 4828.86,2094.14 5582.72,1340.28 5582.72,906.72 5526,850 5440,850 5426,864 5426,949 P2.25
RXD2: P4.25 U1.34 | length 4705.8
  Top Layer w9.84: v1(447,1051) 521,1125 521,2424 591.41,2494.41 U1.34
  Bottom Layer w9.84: P4.25 -49,1051 v1(447,1051)
SPIN: P2.28 U1.86 | length 2325.8
  Top Layer w9.84: U1.86 4042.59,2376.3 4117.28,2301.61 4117.28,2220.57 4172.57,2165.28 4187.72,2165.28 4188,2165 4920,2165 v1(5427,1658)
  Bottom Layer w9.84: P2.28 5375,1605 v1@5428,1658
SPIN0: P4.28 U1.59 | length 4373.7
  Top Layer w9.84: v1(966,1224) 1138,1052 v1(1630,1052) ; v1(2139,1052) 2139,1398.05 2505.23,1764.28 2890.28,1764.28 3079.42,1953.42 3362.69,1953.42 3447.27,2038 U1.59
  Bottom Layer w9.84: P4.28 -57.68,1342.32 847.68,1342.32 v1(966,1224) ; v1(1630,1052) v1(2139,1052)
START1: P2.1 P2.26 U1.99 | length 3589.4
  Top Layer w9.84: U1.99 3878.21,2632.21 4103,2857 4723,2857 v1(5833.5,1746.5)
  Bottom Layer w9.84: P2.26 5425,1050 5583,1050 5701,1168 5701,1614 v1(5833.5,1746.5)
START01: P4.26 U1.39 | length 4329.5
  Top Layer w9.84: v1(813,1150) 813,1947 1126.72,2260.72 3014.72,2260.72 3149.99,2395.99 U1.39
  Bottom Layer w9.84: P4.26 -50,1150 v1(813,1150)
STOP1: P2.12 U1.87 | length 2792.9
  Top Layer w9.84: U1.87 4047.96,2395.99 4135,2308.95 4135,2227.91 4179.91,2183 4981.48,2183 v1(5647.48,1517) v1@5649.24,1515.24
  Bottom Layer w9.84: P2.12 5592,1100 5649,1157 v1@5649,1517
STOP01: P4.12 U1.40 | length 4229.9
  Top Layer w9.84: v1(815,1109) 841,1135 841,1949.95 1134.05,2243 3022.05,2243 3155.36,2376.3 U1.40
  Bottom Layer w9.84: P4.12 9,1109 v1@813,1109
TXD0: P2.10 U1.80 | length 2590.5
  Top Layer w9.84: U1.80 3882.13,2258.19 4063.9,2076.42 4810.58,2076.42 5565,1322 5565,982 5483,900 P2.10
TXD2: P4.10 U1.33 | length 4639.5
  Top Layer w9.84: P4.10 238,900 500,1162 500,2434 580.1,2514.1 U1.33
UN: P2.7 U1.50 | length 3421.6
  Top Layer w9.84: U1.50 3265.63,2179.45 3277.98,2191.8 3277.98,2191.98 3328,2242 v1(3341,2242)
  Bottom Layer w9.84: v1(3341,2242) 3341,2199 3458.28,2081.72 4041.28,2081.72 4435,1688 5038,1688 5225,1501 5225,748 5323,650 5425,650 P2.7
UN0: P4.7 U1.27 | length 5015.6
  Top Layer w9.84: v1(144.5,981.5) 361,1198 361,2533 493,2665 3101,2665 3133.79,2632.21 U1.27
  Bottom Layer w9.84: P4.7 144.5,744.5 v1(144.5,981.5)
UP: P2.22 U1.47 | length 3321
  Top Layer w9.84: U1.47 3283.51,2238.51 3335,2290 v1(3373,2290)
  Bottom Layer w9.84: v1@3372,2290 3372,2208 3480.57,2099.43 4070.57,2099.43 4458,1712 5059,1712 5255,1516 5255,760 5315,700 P2.22
UP0: P4.22 U1.28 | length 5011.5
  Top Layer w9.84: P4.22 -50,750 -50,916 -14,952 165,952 392,1179 392,2498 535,2641 3087,2641 3115.48,2612.52 U1.28
UP0-: P3.15 R24.1 | length 5029.2
  Top Layer w9.84: P3.15 1878,-22 1403,-22 749,632 749,2064.95 998.05,2314 2787,2314 R24.1
UP-: P1.15 P2.2 R12.1 R26.1 | length 7638.6
  Top Layer w9.84: R26.1 4327.28,1866.72 4883.34,1866.72 5243,1507.05 5243,-13 5278.67,-48.67 7350.33,-48.67 7375,-24 P1.15 ; R12.1 4317,2003 4806,2003 5289,1520 5289,75 5309,55 5430,55 P2.2
VN: P2.6 U1.49 | length 3636.1
  Top Layer w9.84: v1(3157,2139) 3157,2170.15 3185.99,2199.14 U1.49
  Bottom Layer w9.84: v1(3157,2139) 3157,2027 3200,1984 4056,1984 4411,1629 5022,1629 5150,1501 5150,713 5315,548 5427,548 P2.6
VN0: P4.6 U1.25 | length 5516.4
  Top Layer w9.84: P4.6 -54,554 -180,554 -223.57,597.57 -223.57,1387.43 279,1890 279,2571 423.87,2715.87 U1.25
VOL_1: C35.1 P7.11 P7.12 U1.8 | length 3951.2
  Top Layer w9.84: U1.8 3624.43,2911.43 3664.5,2951.5 3707.5,2951.5 C35.1 3785,3029 3785,3063.51 3919.49,3198 6888,3198 6944,3142 P7.11
  Bottom Layer w9.84: P7.12 P7.11
VOL_2: C34.1 P7.9 P7.10 U1.9 | length 4174.3
  Top Layer w9.84: U1.9 3604.75,2923.75 3665.99,2984.99 3702,3021 3702,3164 3764,3226 6976,3226 7044,3158 P7.9
  Bottom Layer w9.84: P7.10 P7.9
VOL_ADC: C15.2 P1.3 R42.2 U1.74 | length 6033.7
  Top Layer w9.84: U1.74 3742.54,2000.46 3946,1797 R42.2 C15.2 3965,1707 3989,1683 4988,1683 5176.31,1494.69 5176.31,-33.31 5244.98,-101.98 7495.02,-101.98 7540,-57 v1(7540,50)
  Bottom Layer w9.84: P1.3 7540,135 v1(7540,50)
VOL_ADC0: C16.2 P3.3 R43.2 U1.58 | length 3040.8
  Top Layer w9.84: P3.3 1999,200 1950,249 1950,329 1972,351 2070,351 2112,393 2112,1415 2479,1782 2837,1782 2865,1810 R43.2 2865,1864.67 C16.2 2962.67,1865.67 3068.14,1971.14 3355.35,1971.14 3427.58,2043.37 U1.58
VP: P2.21 U1.46 | length 3482
  Top Layer w9.84: U1.46 3271,2258.19 3334.8,2322 v1(3344,2322)
  Bottom Layer w9.84: v1(3344,2322) 3304,2282 3304,2190 3430,2064 4021,2064 4429,1656 5034,1656 5184,1506 5184,722 5306,600 P2.21
VP0: P4.21 U1.26 | length 5170.6
  Top Layer w9.84: P4.21 -177,677 -177,1387 315,1879 315,2559 440,2684 3193.71,2684 U1.26
VP0-: P4.15
VP-: P2.15
WN: P2.5 U1.48 | length 3848.2
  Top Layer w9.84: v1(3095,2171) 3116,2171 3163.82,2218.82 U1.48
  Bottom Layer w9.84: v1(3095,2171) 3095,1988 3145,1938 4005,1938 4373,1570 5016,1570 5098,1488 5098,674 5325,447 5428,447 P2.5
WN0: P4.5 U1.23 | length 5852.1
  Top Layer w9.84: P4.5 -50,450 -226,450 -286,510 -286,1427 243.57,1956.57 243.57,2585.68 445.61,2787.72 3302.5,2787.72 3329.16,2761.06 U1.23
WP: P2.20 U1.45 | length 3691
  Top Layer w9.84: v1(3124.5,2225.5) 3176.88,2277.88 U1.45
  Bottom Layer w9.84: v1@3126,2225.5 3126,1996 3161,1961 4031,1961 4394,1598 5020,1598 5120,1498 5120,696 5316,500 P2.20
WP0: P4.20 U1.24 | length 5585
  Top Layer w9.84: P4.20 -193,500 -256,563 -256,1395.05 261.28,1912.34 261.28,2578.34 452.95,2770 3295.16,2770 3309.47,2755.69 U1.24
WP0-: P4.16 R2.1 | length 5174.3
  Top Layer w9.84: P4.16 -57.68,57.68 31.68,57.68 56.28,82.28 554.34,82.28 664.72,192.66 664.72,2360.66 724.34,2420.28 2782.24,2420.28 2786.24,2424.28 2787.72,2424.28 R2.1
WP-: P2.16 R4.1 | length 2701.2
  Top Layer w9.84: R4.1 4331,2022 4812.05,2022 5306.72,1527.34 5306.72,115.28 5322,100 P2.16
pads on no net: P1.17 P1.18 P1.22 P1.23 P1.25 P2.8 P2.9 P2.11 P2.18 P2.19 P2.23 P2.24 P2.27 P3.5 P3.17 P3.18 P3.22 P3.23 P3.25 P4.8 P4.9 P4.11 P4.18 P4.19 P4.23 P4.24 P4.27 P6.6 P6.8 P6.9 P6.10 U1.5 U1.29 U1.60 U1.72

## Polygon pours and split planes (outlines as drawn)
+3.3V on Top Layer "NONET_L-01_P-001" (solid, remove dead copper, pour order 12): 6449,2092 6465,2108 7156,2108 7156,1967 7149,1960 6454,1960 6448,1966
GND on Top Layer "Bottom Layer-No Net" (solid, remove dead copper, pour order 11): 7457,1334 7416,1375 6911,1375 6911,1074 6921,1064 7506,1064 7506,1285 7457,1334
GND on Bottom Layer "Bottom Layer-No Net" (solid, remove dead copper, pour order 2): -465.05,3348 -465.05,261 -420.05,216 -404.05,200 297.95,200 7786.95,200 7832.95,246 7896.95,310 7896.95,3394
GND on Bottom Layer "Bottom Layer-No Net" (solid, remove dead copper, pour order 8): 5185,207.74 6972.34,207.74 7118.64,207.74 7353.98,292 7430.31,264.67 7707,264.67 7707,-50.73 7586.15,-94 7582.97,-92.86 5188.18,-92.86

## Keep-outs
Keep-Out Layer:
  circle w3.94: c-291,3164 r78.74
  lines w3.94: 2623.01,3396.67 2624.01,3395.67 ; -440,-91 ccw(c-324,-91) -324,-207 2288.99,-207 ccw(c2288.99,-143.67) 2352.32,-143.67 2352.32,1448.33 cw(c2392,1448.33) 2392,1488.01 5018,1488.01 cw(c5018,1446.67) 5059.33,1446.67 5059.33,-146.33 ccw(c5121,-146.33) 5121,-208 7669,-208 ccw(c7669,-137) 7740,-137 7740,3235 ccw(c7654.99,3235) 7654.99,3320.01 -294.32,3320.01 ccw(c-294.32,3174.33) -440,3174.33 -440,-91

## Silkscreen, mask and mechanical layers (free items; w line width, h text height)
Top Overlay:
  drawing of 7 lines, arcs and shapes, not listed
  text "LKS_EVB_MCU451_V1.0" at 207,3107 h100
  text "5V" at 6777,3046 h79.92 r90
  text "JDQ" at 7466,3045 h79.92 r90
  text "Curr" at 7372,3040 h79.92 r90
  text "PWM" at 7175,3038 h79.92 r90
  text "GND" at 6670,3033 h79.92 r90
  text "12V" at 6871,3033 h79.92 r90
  text "GND" at 6567,3032 h79.92 r90
  text "过流" at 7271,3032 h79.92 r90
  text "Vol2" at 7078,3031 h79.92 r90
  text "Vol1" at 6973,3030 h79.92 r90
  text "GND" at 2508,2793 h79.92
  text "D" at 2690,2793 h79.92
  text "C" at 2784,2792 h79.92
  text "3.3V" at 2851,2792 h79.92
  text "RNST" at -276,2726 h79.92
  text "TDI" at -216.06,2654 h79.92
  text "TMS" at -249.21,2552 h79.92
  text "TCLK" at -268.23,2452 h79.92
  text "TDO" at -250.69,2246 h79.92
  text "LED01" at 95.07,1287.74 h80
  text "LED1" at 5560.07,1282 h80
  text "SPIN0" at -366,1280 h79.92
  text "GND" at 1698.07,1274.74 h80
  text "SPIN" at 5117,1271 h79.92
  text "GND" at 7539,1266 h79.92
  text "GND" at 2073,1264 h79.92
  text "LED2" at 5564.07,1184 h80
  text "LED02" at 87.07,1181.74 h80
  text "GND" at 1693.07,1174.74 h80
  text "GND" at 2072,1166 h79.92
  text "GND" at 7535,1161 h79.92
  text "STOP01" at 88,1083.74 h80
  text "STOP1" at 5565,1082.74 h80
  text "START01" at -401,1076.74 h80
  text "GND" at 1693.07,1076.74 h80
  text "START1" at 5096,1074.74 h80
  text "GND" at 2073,1073 h79.92
  text "GND" at 7540,1067 h79.92
  text "RXD0" at 5146.07,979.74 h80
  text "RXD2" at -369.93,975 h80
  text "TXD2" at 83,881 h80
  text "TXD0" at 5552,879.74 h80
  text "H_U" at 7542,676 h79.92
  text "H_U0" at 2071,673 h79.92
  text "UP0" at -316,669 h79.92
  text "UP" at 5219,661 h79.92
  text "H_V" at 7540,578 h79.92
  text "UN0" at 75,570 h79.92
  text "UN" at 5551,567 h79.92
  text "VP" at 5216,565 h79.92
  text "VP0" at -318,562 h79.92
  text "H_V0" at 2072,562 h79.92
  text "H_W" at 7541,474 h79.92
  text "H_W0" at 2069,466 h79.92
  text "VN0" at 80,464 h79.92
  text "WP" at 5212,461 h79.92
  text "VN" at 5554,459 h79.92
  text "WP0" at -312,457 h79.92
  text "WN0" at 83,367 h79.92
  text "WN" at 5561,352 h79.92
  text "PU" at 5566,265 h79.92
  text "PU0" at 67,264 h79.92
  text "PV" at 5567,169 h79.92
  text "Vol" at 2085,166 h79.92
  text "PV0" at 66,164 h79.92
  text "PW0" at -334,161 h79.92
  text "Vol" at 7556,158 h79.92
  text "PW" at 5208,157 h79.92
